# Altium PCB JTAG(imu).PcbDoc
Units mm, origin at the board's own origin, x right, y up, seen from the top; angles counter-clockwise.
Board outline 152.4 x 101.6 mm, 2 copper layers (Top Layer, Bottom Layer); 2 components, 8 nets, 28 pads, 0 vias.
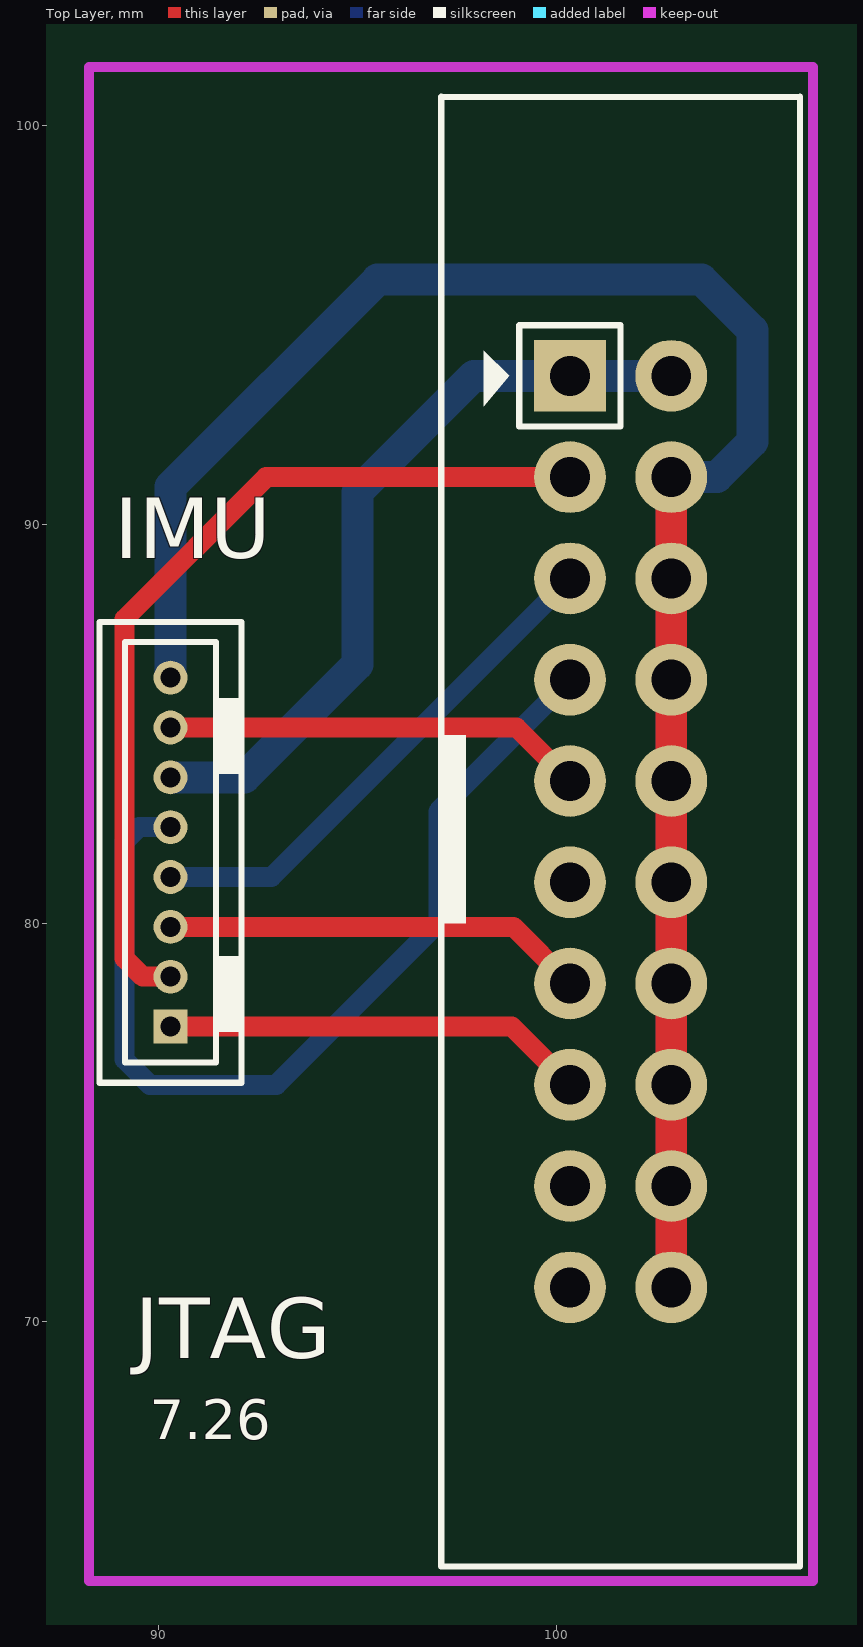
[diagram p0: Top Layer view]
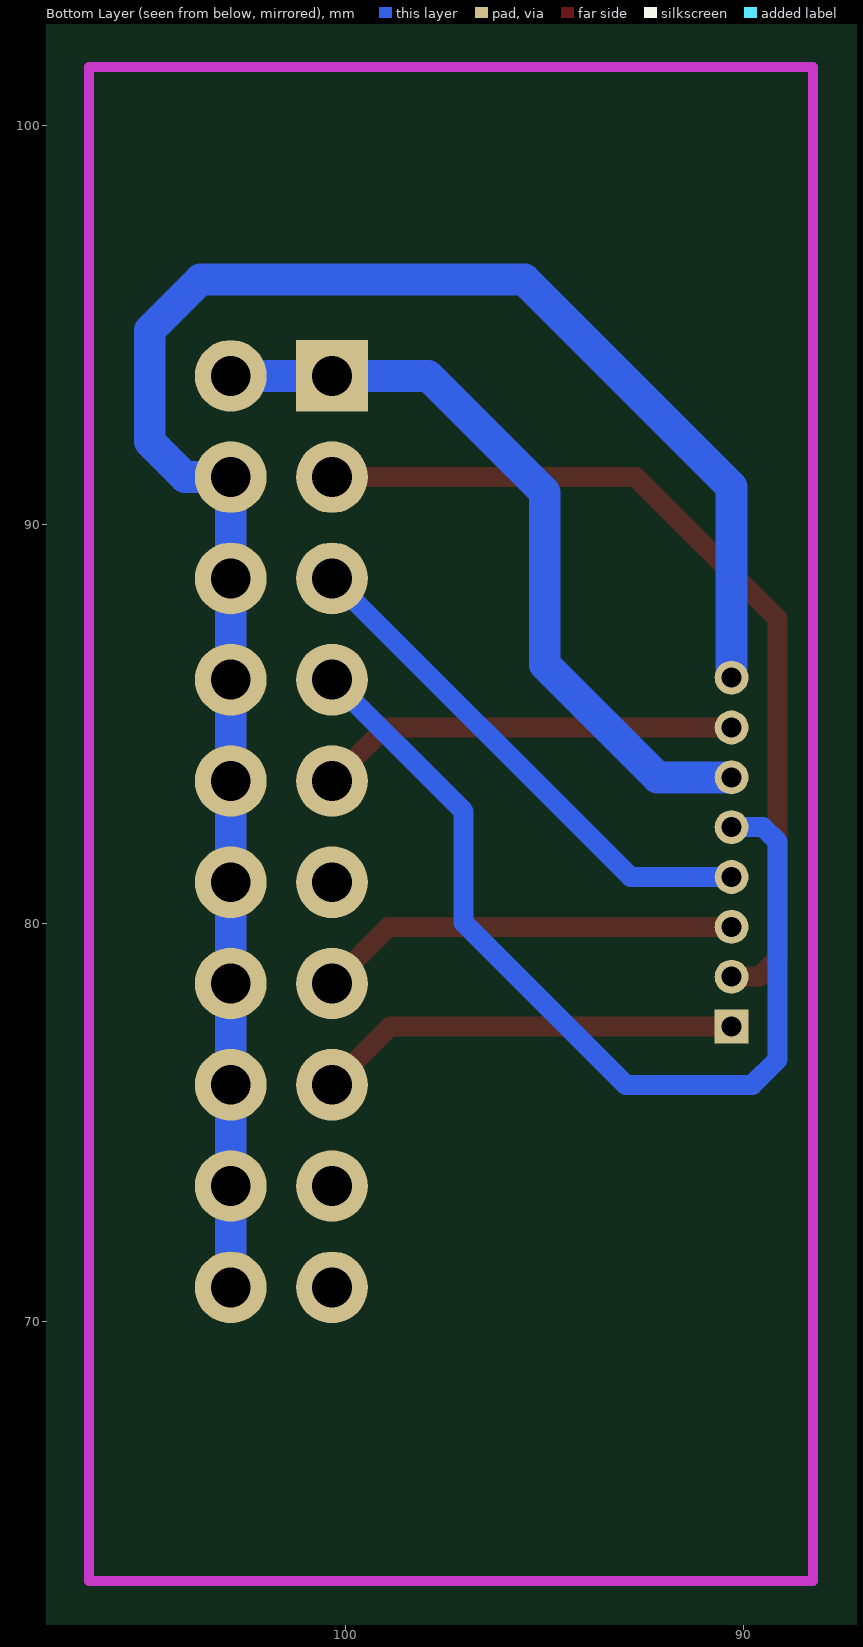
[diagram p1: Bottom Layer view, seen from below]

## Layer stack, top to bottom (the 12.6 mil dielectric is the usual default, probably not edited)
Top Layer: signal copper 0.0356
Dielectric: dielectric 0.32, FR-4, Dk 4.8
Bottom Layer: signal copper 0.0356

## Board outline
25.4,25.4 177.8,25.4 177.8,127 25.4,127

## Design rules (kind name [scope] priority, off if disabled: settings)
Clearance [All] p1: gap=0.254
PolygonConnect [All] p1: connectstyle=Relief reliefconductorwidth=0.254 reliefentries=4 polygonreliefangle="90 Angle"
RoutingVias [All] p1: holewidth=0.711 width=1.27 viastyle="Through Hole" minholewidth=0.711 minwidth=1.27 maxholewidth=0.711 maxwidth=1.27
SilkscreenOverComponentPads [All] p1: minsilkscreentomaskgap=0.254
SolderMaskExpansion [All] p1: expansion=0.102
Width [All] p1: maxlimit=1 minlimit=0.254 preferedwidth=0.254
27 further rules are at their usual default settings.

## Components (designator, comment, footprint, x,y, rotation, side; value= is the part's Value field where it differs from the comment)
IMU "CON-SIP8-2.0" PLUG1.27-8P 90.424,83.312 r270 top (schematic designator IMU-jtag)
P2 "PLUG-20S" PLUG-20S 101.6,82.296 r270 top

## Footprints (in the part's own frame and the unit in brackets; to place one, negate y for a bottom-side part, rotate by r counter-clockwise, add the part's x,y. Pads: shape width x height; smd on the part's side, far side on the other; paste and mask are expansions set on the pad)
PLUG1.27-8P [mm]
  round 0.85 hole 0.5: 1(-2.845,-0.114) 2(-1.595,-0.114) 3(-0.345,-0.114) 4(0.905,-0.114) 5(2.155,-0.114) 6(3.405,-0.114) 7(4.655,-0.114)
  rect 0.85x0.85 hole 0.5: 8(5.905,-0.114)
  silkscreen extent -4.24,-1.89 7.32,1.66
PLUG-20S [mm] "20P2.54mm  simple"
  rect 1.8x1.8 hole 1: 1(-11.43,-1.27)
  round 1.8 hole 1: 2(-11.43,1.27) 3(-8.89,-1.27) 4(-8.89,1.27) 5(-6.35,-1.27) 6(-6.35,1.27) 7(-3.81,-1.27) 8(-3.81,1.27) 9(-1.27,-1.27) 10(-1.27,1.27) 11(1.27,-1.27) 12(1.27,1.27) 13(3.81,-1.27) 14(3.81,1.27) 15(6.35,-1.27) 16(6.35,1.27) 17(8.89,-1.27) 18(8.89,1.27) 19(11.43,-1.27) 20(11.43,1.27)
  silkscreen extent -18.43,-4.5 18.43,4.5

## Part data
IMU: "单排针8PIN"
P2: library part "Header 10X2H", "Header, 10-Pin, Dual row, Right Angle"

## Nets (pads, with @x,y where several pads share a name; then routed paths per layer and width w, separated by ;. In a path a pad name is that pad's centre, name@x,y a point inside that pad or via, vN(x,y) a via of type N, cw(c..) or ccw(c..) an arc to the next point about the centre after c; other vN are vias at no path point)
GND: IMU.1 P2.4 P2.6 P2.8 P2.10 P2.12 P2.14 P2.16 P2.18 P2.20 | length 67.9
  Top Layer w0.8: P2.20 P2.18 P2.16 P2.14 P2.12 P2.10 P2.8 P2.6 P2.4
  Bottom Layer w0.8: IMU.1 90.31,90.945 95.504,96.139 103.632,96.139 104.902,94.869 104.902,92.075 104.013,91.186 P2.4 P2.6 P2.8 P2.10 P2.12 P2.14 P2.16 P2.18 P2.20
NetIMU-jtag_2: IMU.2 P2.9 | length 10.6
  Top Layer w0.5: IMU.2 98.989,84.907 P2.9
NetIMU-jtag_3: IMU.3 P2.1 P2.2 | length 19.3
  Bottom Layer w0.5: IMU.3 IMU.3@90.374,83.657
  Bottom Layer w0.8: IMU.3@90.374,83.657 92.166,83.657 94.996,86.487 94.996,90.805 97.917,93.726 P2.1 P2.2
NetIMU-jtag_4: IMU.4 P2.7 | length 24.3
  Bottom Layer w0.5: IMU.4 89.519,82.407 89.154,82.042 89.154,76.581 89.789,75.946 92.964,75.946 97.028,80.01 97.028,82.804 P2.7 P2.7@100.33,85.864
NetIMU-jtag_5: IMU.5 P2.5 | length 13.1
  Bottom Layer w0.5: IMU.5 92.841,81.157 P2.5
NetIMU-jtag_6: IMU.6 P2.13 | length 10.6
  Top Layer w0.5: IMU.6 98.909,79.907 P2.13
NetIMU-jtag_7: IMU.7 P2.3 | length 22.5
  Top Layer w0.5: IMU.7 89.614,78.657 89.154,79.117 89.154,87.63 92.71,91.186 P2.3
NetIMU-jtag_8: IMU.8 P2.15 | length 10.6
  Top Layer w0.5: IMU.8 98.869,77.407 P2.15
pads on no net: P2.11 P2.17 P2.19

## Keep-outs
Keep-Out Layer:
  lines w0.254: 88.265,63.5 106.426,63.5 106.426,101.473 88.265,101.473 88.265,63.5

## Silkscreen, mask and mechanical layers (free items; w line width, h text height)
Top Overlay:
  text "JTAG" at 89.408,69.088 h1.52
  text "7.26" at 89.789,67.056 h1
